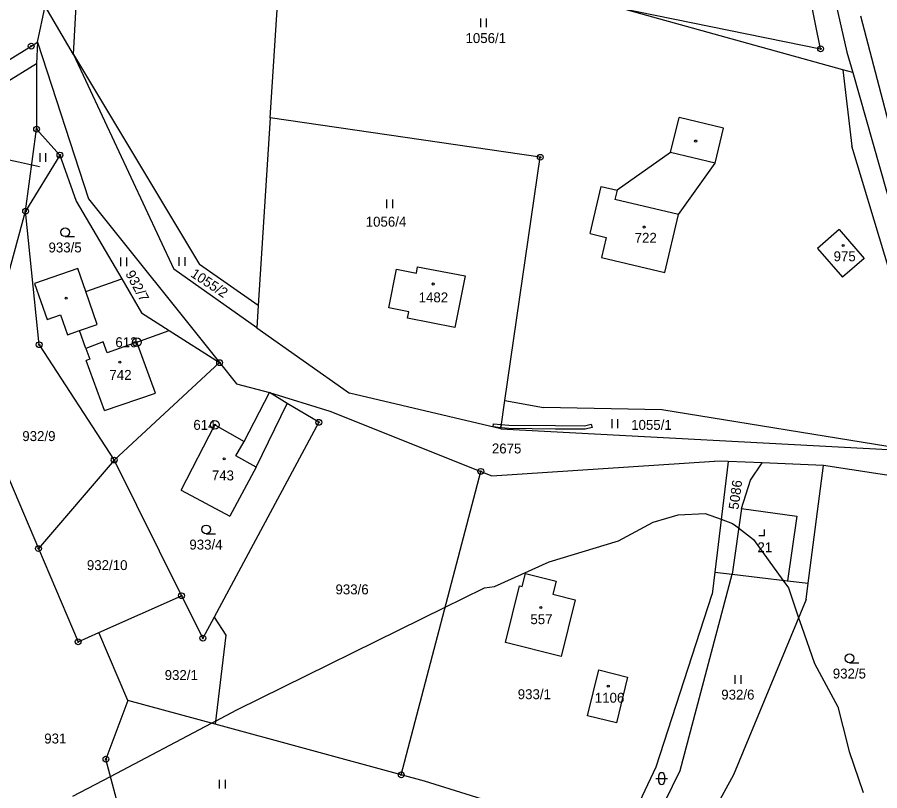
# Model space of a CAD drawing. Extents: x -439246 to -433691, y -1130252 to -1121148.
# Drawn here: x -438498.3 to -438350.5, y -1124101.8 to -1123969.3 of the extents above; entities that cross this region are included whole.
import ezdxf

# ---------------------------------------------------------------- set-up
doc = ezdxf.new("R2010")
doc.units = 0
for name, color, linetype in [('Vrstva 1', 7, 'Continuous'), ('Vrstva 16', 7, 'Continuous'), ('Vrstva 17', 7, 'Continuous'), ('Vrstva 18', 7, 'Continuous'), ('Vrstva 19', 7, 'Continuous'), ('Vrstva 24', 7, 'Continuous'), ('Vrstva 25', 7, 'Continuous'), ('Vrstva 3', 7, 'Continuous'), ('Vrstva 30', 7, 'Continuous'), ('Vrstva 37', 7, 'Continuous'), ('Vrstva 4', 7, 'Continuous'), ('Vrstva 52', 7, 'Continuous')]:
    doc.layers.add(name, color=color, linetype=linetype)

msp = doc.modelspace()

# ---------------------------------------------------------------- linework, layer by layer
at = {"layer": 'Vrstva 1'}
for p, q in [((-438356.83, -1123978.32), (-438395.18, -1123967.69)), ((-438355.13, -1123978.79), (-438356.83, -1123978.32)), ((-438356.83, -1123978.32), (-438355.27, -1123991.36)), ((-438355.13, -1123978.79), (-438341.27, -1124027.67)), ((-438408.67, -1123993.28), (-438454.94, -1123986.52)), ((-438414.75, -1124034.93), (-438408.67, -1123993.28)), ((-438415.46, -1124039.77), (-438414.75, -1124034.93)), ((-438414.75, -1124034.93), (-438408.13, -1124036.13)), ((-438411.76, -1124066.81), (-438411.21, -1124064.58)), ((-438411.21, -1124064.58), (-438405.95, -1124065.88)), ((-438405.95, -1124065.88), (-438406.51, -1124068.12)), ((-438414.65, -1124076.4), (-438412.26, -1124066.7)), ((-438412.26, -1124066.7), (-438411.76, -1124066.81)), ((-438406.51, -1124068.12), (-438402.72, -1124069.06)), ((-438402.72, -1124069.06), (-438405.12, -1124078.8)), ((-438405.12, -1124078.8), (-438414.65, -1124076.4)), ((-438400.58, -1124088.94), (-438398.63, -1124081.08)), ((-438398.63, -1124081.08), (-438393.7, -1124082.35)), ((-438393.7, -1124082.35), (-438395.61, -1124090.15)), ((-438395.61, -1124090.15), (-438400.58, -1124088.94))]:
    msp.add_line(p, q, dxfattribs=at)
for points in [[(-438454.94, -1123986.52), (-438448.81, -1123891.13)], [(-438488.65, -1123975.66), (-438484.51, -1123899.32)], [(-438360.64, -1123955.33), (-438356.12, -1123975.29)], [(-438360.63, -1123974.7), (-438363.48, -1123960.84)], [(-438494.83, -1123973.57), (-438493.54, -1123967.38)], [(-438488.65, -1123975.66), (-438493.54, -1123967.38)], [(-438395.18, -1123967.69), (-438360.63, -1123974.7)], [(-438353.8, -1123969.08), (-438337.95, -1124029.47)], [(-438523.97, -1123991.56), (-438495.91, -1123974.24)], [(-438495.91, -1123974.24), (-438494.83, -1123973.57)], [(-438494.83, -1123973.57), (-438494.99, -1123977.22)], [(-438494.83, -1123973.57), (-438486.12, -1124000.38)], [(-438488.65, -1123975.66), (-438471.5, -1124012.45)], [(-438488.65, -1123975.66), (-438467.06, -1124011.66)], [(-438356.12, -1123975.29), (-438355.13, -1123978.79)], [(-438522.77, -1123994.36), (-438494.99, -1123977.22)], [(-438494.99, -1123977.22), (-438494.99, -1123988.47)], [(-438454.94, -1123986.52), (-438457.01, -1124018.66)], [(-438386.35, -1123992.48), (-438384.9, -1123986.48)], [(-438377.27, -1123988.32), (-438384.9, -1123986.48)], [(-438496.87, -1124002.53), (-438494.99, -1123988.47)], [(-438494.99, -1123988.47), (-438490.99, -1123992.9)], [(-438378.72, -1123994.32), (-438377.27, -1123988.32)], [(-438343.98, -1124028.81), (-438355.27, -1123991.36)], [(-438490.99, -1123992.9), (-438496.87, -1124002.53)], [(-438490.99, -1123992.9), (-438488.22, -1124000.79)], [(-438386.35, -1123992.48), (-438395.51, -1123998.92)], [(-438384.99, -1124003.09), (-438378.72, -1123994.32)], [(-438400.14, -1124006.36), (-438398.24, -1123998.28)], [(-438398.24, -1123998.28), (-438395.51, -1123998.92)], [(-438488.22, -1124000.79), (-438480.41, -1124014.13)], [(-438486.12, -1124000.38), (-438463.63, -1124028.46)], [(-438505.62, -1124034.62), (-438496.87, -1124002.53)], [(-438494.55, -1124025.39), (-438496.87, -1124002.53)], [(-438387.34, -1124013.02), (-438384.99, -1124003.09)], [(-438400.14, -1124006.36), (-438397.41, -1124007)], [(-438357.44, -1124005.68), (-438361.15, -1124008.88)], [(-438357.44, -1124005.68), (-438353.2, -1124010.6)], [(-438397.41, -1124007), (-438398.18, -1124010.47)], [(-438361.15, -1124008.88), (-438356.91, -1124013.8)], [(-438398.18, -1124010.47), (-438387.34, -1124013.02)], [(-438353.2, -1124010.6), (-438356.91, -1124013.8)], [(-438487.95, -1124012.31), (-438495.36, -1124014.9)], [(-438486.57, -1124016.28), (-438487.95, -1124012.31)], [(-438457.25, -1124022.51), (-438471.5, -1124012.45)], [(-438457.01, -1124018.66), (-438467.06, -1124011.66)], [(-438434.63, -1124019.09), (-438433.33, -1124012.45)], [(-438433.33, -1124012.45), (-438429.91, -1124013.13)], [(-438429.91, -1124013.13), (-438429.69, -1124012.02)], [(-438429.69, -1124012.02), (-438421.57, -1124013.61)], [(-438486.57, -1124016.28), (-438480.41, -1124014.13)], [(-438480.41, -1124014.13), (-438477.01, -1124019.92)], [(-438421.57, -1124013.61), (-438423.29, -1124022.46)], [(-438495.36, -1124014.9), (-438493.2, -1124021.08)], [(-438457.01, -1124018.66), (-438457.25, -1124022.51)], [(-438493.2, -1124021.08), (-438490.89, -1124020.27)], [(-438490.89, -1124020.27), (-438489.71, -1124023.67)], [(-438477.01, -1124019.92), (-438472.27, -1124022.94)], [(-438431.19, -1124019.78), (-438434.63, -1124019.09)], [(-438431.41, -1124020.86), (-438431.19, -1124019.78)], [(-438423.29, -1124022.46), (-438431.41, -1124020.86)], [(-438489.71, -1124023.67), (-438487.62, -1124022.97)], [(-438486.57, -1124026.01), (-438487.62, -1124022.97)], [(-438477.8, -1124024.95), (-438472.27, -1124022.94)], [(-438472.27, -1124022.94), (-438463.63, -1124028.46)], [(-438457.25, -1124022.51), (-438441.39, -1124033.7)], [(-438494.55, -1124025.39), (-438481.71, -1124045.14)], [(-438486.57, -1124026.01), (-438485.88, -1124027.89)], [(-438474.63, -1124033.67), (-438477.8, -1124024.95)], [(-438485.88, -1124027.89), (-438486.48, -1124028.11)], [(-438483.38, -1124036.64), (-438486.48, -1124028.11)], [(-438463.63, -1124028.46), (-438481.71, -1124045.14)], [(-438463.63, -1124028.46), (-438460.72, -1124032.1)], [(-438460.72, -1124032.1), (-438455.09, -1124033.59)], [(-438505.62, -1124034.62), (-438494.67, -1124060.31)], [(-438483.38, -1124036.64), (-438474.63, -1124033.67)], [(-438459.41, -1124041.94), (-438455.09, -1124033.59)], [(-438452.05, -1124035.43), (-438455.09, -1124033.59)], [(-438455.09, -1124033.59), (-438444.75, -1124036.78)], [(-438415.46, -1124039.77), (-438441.39, -1124033.7)], [(-438457.38, -1124046.37), (-438452.05, -1124035.43)], [(-438446.63, -1124038.68), (-438452.05, -1124035.43)], [(-438387.84, -1124036.53), (-438408.13, -1124036.13)], [(-438347.01, -1124043.14), (-438387.84, -1124036.53)], [(-438444.75, -1124036.78), (-438418.87, -1124047.08)], [(-438470.22, -1124050.31), (-438464.42, -1124039.1)], [(-438446.63, -1124038.68), (-438464.57, -1124072.07)], [(-438464.42, -1124039.1), (-438459.41, -1124041.94)], [(-438415.46, -1124039.77), (-438344.79, -1124043.55)], [(-438481.71, -1124045.14), (-438494.67, -1124060.31)], [(-438481.71, -1124045.14), (-438470.15, -1124068.38)], [(-438416.98, -1124047.83), (-438378.82, -1124045.31)], [(-438376.5, -1124045.4), (-438378.82, -1124045.31)], [(-438376.5, -1124045.4), (-438378.76, -1124064.33)], [(-438370.65, -1124045.64), (-438376.5, -1124045.4)], [(-438457.38, -1124046.37), (-438461.9, -1124054.78)], [(-438372.65, -1124048.59), (-438370.65, -1124045.64)], [(-438360.12, -1124046.06), (-438370.65, -1124045.64)], [(-438362.74, -1124066.25), (-438360.12, -1124046.06)], [(-438335.1, -1124049.91), (-438360.12, -1124046.06)], [(-438432.5, -1124099.07), (-438418.87, -1124047.08)], [(-438418.87, -1124047.08), (-438416.98, -1124047.83)], [(-438374.2, -1124053.42), (-438372.65, -1124048.59)], [(-438470.22, -1124050.31), (-438461.9, -1124054.78)], [(-438374.2, -1124053.42), (-438375.81, -1124064.69)], [(-438494.67, -1124060.31), (-438487.87, -1124076.28)], [(-438378.76, -1124064.33), (-438379.21, -1124068.13)], [(-438378.76, -1124064.33), (-438375.81, -1124064.69)], [(-438384.7, -1124098.3), (-438375.81, -1124064.69)], [(-438375.81, -1124064.69), (-438366.3, -1124065.83)], [(-438366.3, -1124065.83), (-438362.74, -1124066.25)], [(-438363.1, -1124069.04), (-438362.74, -1124066.25)], [(-438484.31, -1124074.69), (-438470.15, -1124068.38)], [(-438470.15, -1124068.38), (-438466.49, -1124075.64)], [(-438388.84, -1124097.68), (-438379.21, -1124068.13)], [(-438363.1, -1124069.04), (-438375.57, -1124099.06)], [(-438464.57, -1124072.07), (-438466.49, -1124075.64)], [(-438464.57, -1124072.07), (-438462.54, -1124075.14)], [(-438487.87, -1124076.28), (-438484.31, -1124074.69)], [(-438479.34, -1124086.32), (-438484.31, -1124074.69)], [(-438462.54, -1124075.14), (-438464.39, -1124090.39)], [(-438479.34, -1124086.32), (-438483.1, -1124096.37)], [(-438464.39, -1124090.39), (-438479.34, -1124086.32)], [(-438432.5, -1124099.07), (-438464.39, -1124090.39)], [(-438477, -1124119.25), (-438483.1, -1124096.37)], [(-438394.91, -1124110.63), (-438388.84, -1124097.68)], [(-438391.25, -1124111.75), (-438384.7, -1124098.3)], [(-438428.54, -1124100.15), (-438432.5, -1124099.07)], [(-438375.57, -1124099.06), (-438383.79, -1124114.05)], [(-438399.02, -1124109.36), (-438428.54, -1124100.15)]]:
    msp.add_lwpolyline(points, dxfattribs=at)
at = {"layer": 'Vrstva 16'}
msp.add_line((-438498.1, -1123994.14), (-438501.03, -1123993.51), dxfattribs=at)
msp.add_lwpolyline([(-438494.51, -1123994.91), (-438498.1, -1123994.14)], dxfattribs=at)
at = {"layer": 'Vrstva 24'}
for centre, radius in [((-438495.91, -1123974.24), 0.5), ((-438495.91, -1123974.24), 0.1), ((-438360.63, -1123974.7), 0.5), ((-438360.63, -1123974.7), 0.1), ((-438494.99, -1123988.47), 0.5), ((-438494.99, -1123988.47), 0.1), ((-438490.99, -1123992.9), 0.5), ((-438490.99, -1123992.9), 0.1), ((-438408.67, -1123993.28), 0.5), ((-438408.67, -1123993.28), 0.1), ((-438496.87, -1124002.53), 0.5), ((-438496.87, -1124002.53), 0.1), ((-438477.8, -1124024.96), 0.75), ((-438494.55, -1124025.39), 0.5), ((-438494.55, -1124025.39), 0.1), ((-438477.8, -1124024.96), 0.1), ((-438463.63, -1124028.46), 0.5), ((-438463.63, -1124028.46), 0.1), ((-438464.43, -1124039.12), 0.75), ((-438464.43, -1124039.12), 0.1), ((-438446.63, -1124038.68), 0.5), ((-438446.63, -1124038.68), 0.1), ((-438481.71, -1124045.14), 0.5), ((-438481.71, -1124045.14), 0.1), ((-438418.87, -1124047.08), 0.5), ((-438418.87, -1124047.08), 0.1), ((-438494.67, -1124060.31), 0.5), ((-438494.67, -1124060.31), 0.1), ((-438470.15, -1124068.38), 0.5), ((-438470.15, -1124068.38), 0.1), ((-438487.87, -1124076.28), 0.5), ((-438487.87, -1124076.28), 0.1), ((-438466.49, -1124075.64), 0.5), ((-438466.49, -1124075.64), 0.1), ((-438483.1, -1124096.37), 0.5), ((-438483.1, -1124096.37), 0.1), ((-438432.5, -1124099.07), 0.5), ((-438432.5, -1124099.07), 0.1)]:
    msp.add_circle(centre, radius, dxfattribs=at)
at = {"layer": 'Vrstva 25'}
for p, q in [((-438418.88, -1123971.02), (-438418.88, -1123969.52)), ((-438417.88, -1123971.02), (-438417.88, -1123969.52)), ((-438494.4, -1123994.08), (-438494.4, -1123992.58)), ((-438493.4, -1123994.08), (-438493.4, -1123992.58)), ((-438434.95, -1124002.02), (-438434.95, -1124000.52)), ((-438433.95, -1124002.02), (-438433.95, -1124000.52)), ((-438490.09, -1124006.88), (-438488.49, -1124006.88)), ((-438480.53, -1124011.93), (-438480.53, -1124010.43)), ((-438479.53, -1124011.93), (-438479.53, -1124010.43)), ((-438470.54, -1124011.88), (-438470.54, -1124010.38)), ((-438469.54, -1124011.88), (-438469.54, -1124010.38)), ((-438396.38, -1124039.66), (-438396.38, -1124038.16)), ((-438395.38, -1124039.66), (-438395.38, -1124038.16)), ((-438465.94, -1124057.77), (-438464.34, -1124057.77)), ((-438355.69, -1124079.86), (-438354.09, -1124079.86)), ((-438375.25, -1124083.47), (-438375.25, -1124081.97)), ((-438374.25, -1124083.47), (-438374.25, -1124081.97)), ((-438463.64, -1124101.4), (-438463.64, -1124099.9)), ((-438462.64, -1124101.4), (-438462.64, -1124099.9)), ((-438388.88, -1124099.69), (-438386.88, -1124099.69)), ((-438388.38, -1124100.19), (-438388.38, -1124099.19)), ((-438387.38, -1124099.19), (-438387.38, -1124100.19))]:
    msp.add_line(p, q, dxfattribs=at)
msp.add_lwpolyline([(-438371.23, -1124058.04), (-438370.23, -1124058.04), (-438370.23, -1124057.04)], dxfattribs=at)
for centre, radius in [((-438382.05, -1123990.5), 0.175), ((-438490.09, -1124006.13), 0.75), ((-438390.87, -1124005.23), 0.175), ((-438356.76, -1124008.39), 0.175), ((-438427.04, -1124014.99), 0.175), ((-438489.91, -1124017.42), 0.175), ((-438480.74, -1124028.39), 0.175), ((-438462.85, -1124044.94), 0.175), ((-438465.94, -1124057.02), 0.75), ((-438408.58, -1124070.39), 0.175), ((-438355.69, -1124079.11), 0.75), ((-438397.02, -1124083.87), 0.175)]:
    msp.add_circle(centre, radius, dxfattribs=at)
for centre, start, end in [((-438387.88, -1124099.19), 0, 180), ((-438387.88, -1124100.19), 180, 0)]:
    msp.add_arc(centre, 0.5, start, end, dxfattribs=at)
at = {"layer": 'Vrstva 3'}
for points in [[(-438400.14, -1124006.36), (-438398.24, -1123998.28)], [(-438398.24, -1123998.28), (-438395.51, -1123998.92)], [(-438395.51, -1123998.92), (-438395.89, -1124000.53)], [(-438384.99, -1124003.09), (-438395.89, -1124000.53)], [(-438387.34, -1124013.02), (-438384.99, -1124003.09)], [(-438400.14, -1124006.36), (-438397.41, -1124007)], [(-438357.44, -1124005.68), (-438361.15, -1124008.88)], [(-438357.44, -1124005.68), (-438353.2, -1124010.6)], [(-438397.41, -1124007), (-438398.18, -1124010.47)], [(-438361.15, -1124008.88), (-438356.91, -1124013.8)], [(-438398.18, -1124010.47), (-438387.34, -1124013.02)], [(-438353.2, -1124010.6), (-438356.91, -1124013.8)], [(-438434.63, -1124019.09), (-438433.33, -1124012.45)], [(-438433.33, -1124012.45), (-438429.91, -1124013.13)], [(-438429.91, -1124013.13), (-438429.69, -1124012.02)], [(-438429.69, -1124012.02), (-438421.57, -1124013.61)], [(-438421.57, -1124013.61), (-438423.29, -1124022.46)], [(-438431.19, -1124019.78), (-438434.63, -1124019.09)], [(-438431.41, -1124020.86), (-438431.19, -1124019.78)], [(-438423.29, -1124022.46), (-438431.41, -1124020.86)], [(-438483.56, -1124024.92), (-438486.57, -1124026.01)], [(-438486.57, -1124026.01), (-438485.88, -1124027.89)], [(-438482.88, -1124026.8), (-438483.56, -1124024.92)], [(-438477.8, -1124024.95), (-438482.88, -1124026.8)], [(-438474.63, -1124033.67), (-438477.8, -1124024.95)], [(-438485.88, -1124027.89), (-438486.48, -1124028.11)], [(-438483.38, -1124036.64), (-438486.48, -1124028.11)], [(-438483.38, -1124036.64), (-438474.63, -1124033.67)], [(-438470.22, -1124050.31), (-438464.42, -1124039.1)], [(-438464.42, -1124039.1), (-438459.41, -1124041.94)], [(-438460.82, -1124044.42), (-438459.41, -1124041.94)], [(-438457.38, -1124046.37), (-438460.82, -1124044.42)], [(-438457.38, -1124046.37), (-438461.9, -1124054.78)], [(-438470.22, -1124050.31), (-438461.9, -1124054.78)], [(-438411.76, -1124066.81), (-438411.21, -1124064.58)], [(-438411.21, -1124064.58), (-438405.95, -1124065.88)], [(-438405.95, -1124065.88), (-438406.51, -1124068.12)], [(-438414.65, -1124076.4), (-438412.26, -1124066.7)], [(-438412.26, -1124066.7), (-438411.76, -1124066.81)], [(-438406.51, -1124068.12), (-438402.72, -1124069.06)], [(-438402.72, -1124069.06), (-438405.12, -1124078.8)], [(-438405.12, -1124078.8), (-438414.65, -1124076.4)], [(-438400.58, -1124088.94), (-438398.63, -1124081.08)], [(-438398.63, -1124081.08), (-438393.7, -1124082.35)], [(-438393.7, -1124082.35), (-438395.61, -1124090.15)], [(-438395.61, -1124090.15), (-438400.58, -1124088.94)]]:
    msp.add_lwpolyline(points, dxfattribs=at)
at = {"layer": 'Vrstva 30'}
for points in [[(-438416.7, -1124038.93), (-438415.35, -1124039.05), (-438415.44, -1124039.61), (-438416.73, -1124039.47), (-438416.7, -1124038.93)], [(-438399.96, -1124039), (-438399.81, -1124039.58), (-438401.01, -1124039.88), (-438406.09, -1124039.84), (-438414.07, -1124039.76), (-438415.44, -1124039.61)], [(-438415.44, -1124039.61), (-438415.35, -1124039.05), (-438414.05, -1124039.16), (-438406.09, -1124039.24), (-438401.08, -1124039.28), (-438399.96, -1124039)]]:
    msp.add_lwpolyline(points, dxfattribs=at)
at = {"layer": 'Vrstva 37'}
for centre in [(-438390.87, -1124005.23), (-438356.76, -1124008.39), (-438427.04, -1124014.99), (-438480.74, -1124028.39), (-438462.85, -1124044.94), (-438408.58, -1124070.39), (-438397.02, -1124083.87)]:
    msp.add_circle(centre, 0.175, dxfattribs=at)
at = {"layer": 'Vrstva 4'}
for points in [[(-438378.72, -1123994.32), (-438386.35, -1123992.48)], [(-438395.51, -1123998.92), (-438395.89, -1124000.53)], [(-438384.99, -1124003.09), (-438395.89, -1124000.53)], [(-438484.59, -1124021.94), (-438486.57, -1124016.28)], [(-438487.62, -1124022.97), (-438484.59, -1124021.94)], [(-438483.56, -1124024.92), (-438486.57, -1124026.01)], [(-438482.88, -1124026.8), (-438483.56, -1124024.92)], [(-438477.8, -1124024.95), (-438482.88, -1124026.8)], [(-438460.82, -1124044.42), (-438459.41, -1124041.94)], [(-438457.38, -1124046.37), (-438460.82, -1124044.42)], [(-438374.2, -1124053.42), (-438364.72, -1124054.78)], [(-438364.72, -1124054.78), (-438366.3, -1124065.83)]]:
    msp.add_lwpolyline(points, dxfattribs=at)
at = {"layer": 'Vrstva 52'}
msp.add_lwpolyline([(-438488.76, -1124102.73), (-438482.31, -1124099.33), (-438465.03, -1124090.22), (-438464.32, -1124089.84), (-438460.68, -1124087.92), (-438424.97, -1124070.36), (-438421.93, -1124068.86), (-438418.22, -1124067.03), (-438416.52, -1124066.82), (-438407.17, -1124062.57), (-438395.27, -1124058.96), (-438389.32, -1124055.77), (-438386.97, -1124055.07), (-438385.07, -1124054.5), (-438380.4, -1124054.29), (-438377.68, -1124055.28), (-438375.73, -1124055.99), (-438375.18, -1124056.4), (-438374.68, -1124056.78), (-438372.11, -1124058.75), (-438367.1, -1124065.73), (-438366.16, -1124067.03), (-438364.4, -1124072.16), (-438363.91, -1124073.59), (-438361.7, -1124079.99), (-438357.67, -1124087.43), (-438356.84, -1124090.76), (-438355.75, -1124095.08), (-438353.32, -1124102.09)], dxfattribs=at)

# ---------------------------------------------------------------- texts
at = {"layer": 'Vrstva 17'}
for s, p in [('613', (-438481.49, -1124025.81)), ('614', (-438468.13, -1124039.97))]:
    msp.add_text(s, height=1.7, dxfattribs=at).set_placement(p)
at = {"layer": 'Vrstva 18'}
for s, height, p in [('1056/1', 1.7, (-438421.49, -1123973.72)), ('932/11', 0.1, (-438494.71, -1123994.91)), ('1056/4', 1.7, (-438438.59, -1124005.17)), ('933/5', 1.7, (-438492.95, -1124009.58)), ('1055/1', 1.7, (-438393.1, -1124039.97)), ('932/9', 1.7, (-438497.44, -1124041.89)), ('2675', 1.7, (-438416.97, -1124044.01)), ('933/4', 1.7, (-438468.81, -1124060.47)), ('932/10', 1.7, (-438486.37, -1124063.99)), ('933/6', 1.7, (-438443.77, -1124068.15)), ('932/5', 1.7, (-438358.55, -1124082.56)), ('932/1', 1.7, (-438473.04, -1124082.82)), ('933/1', 1.7, (-438412.54, -1124086.1)), ('932/6', 1.7, (-438377.66, -1124086.17)), ('931', 1.7, (-438493.68, -1124093.69))]:
    msp.add_text(s, height=height, dxfattribs=at).set_placement(p)
for s, rotation, p in [('932/7', 298.4728, (-438479.83, -1124013.21)), ('1055/2', 326.6707, (-438468.74, -1124013.62)), ('5086', 82.3781, (-438374.73, -1124053.7))]:
    msp.add_text(s, height=1.7, rotation=rotation, dxfattribs=at).set_placement(p)
at = {"layer": 'Vrstva 19'}
for s, p in [('722', (-438392.5, -1124007.93)), ('975', (-438358.41, -1124011.09)), ('1482', (-438429.52, -1124018.13)), ('742', (-438482.51, -1124031.41)), ('743', (-438464.96, -1124048.63)), ('21', (-438371.46, -1124060.93)), ('557', (-438410.37, -1124073.25)), ('1106', (-438399.33, -1124086.71))]:
    msp.add_text(s, height=1.7, dxfattribs=at).set_placement(p)

doc.saveas('drawing.dxf')
